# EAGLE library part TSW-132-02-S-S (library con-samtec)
THROUGH-HOLE .025" SQ POST HEADER Source: Samtec TSW.pdf
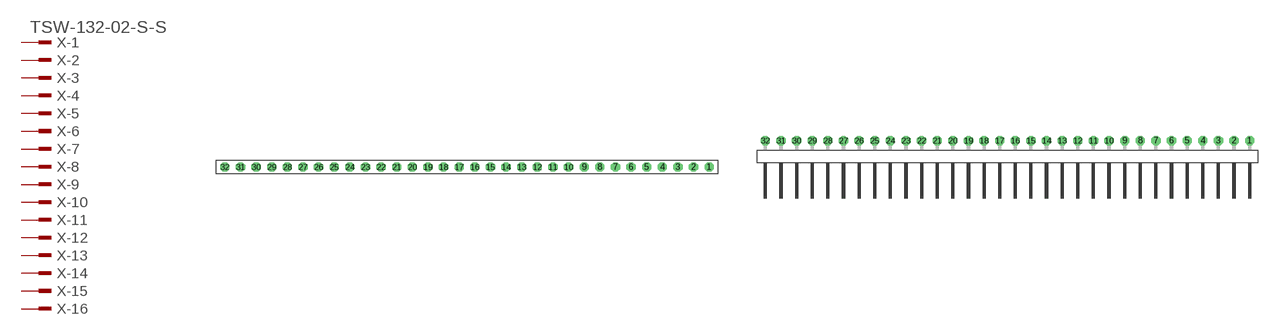
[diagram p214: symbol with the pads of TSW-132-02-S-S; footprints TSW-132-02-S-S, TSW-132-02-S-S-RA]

Designator prefix X; gates -1=MPINV -2=MPIN -3=MPIN -4=MPIN -5=MPIN -6=MPIN -7=MPIN -8=MPIN -9=MPIN -10=MPIN -11=MPIN -12=MPIN -13=MPIN -14=MPIN -15=MPIN -16=MPIN -17=MPIN -18=MPIN -19=MPIN -20=MPIN -21=MPIN -22=MPIN -23=MPIN -24=MPIN -25=MPIN -26=MPIN -27=MPIN -28=MPIN -29=MPIN -30=MPIN -31=MPIN -32=MPIN

## TSW-132-02-S-S (OC_FARNELL: unknown; OC_NEWARK: unknown)  [TSW-132-02-S-S]
1  -1:1  pas
2  -2:1  pas
3  -3:1  pas
4  -4:1  pas
5  -5:1  pas
6  -6:1  pas
7  -7:1  pas
8  -8:1  pas
9  -9:1  pas
10  -10:1  pas
11  -11:1  pas
12  -12:1  pas
13  -13:1  pas
14  -14:1  pas
15  -15:1  pas
16  -16:1  pas
17  -17:1  pas
18  -18:1  pas
19  -19:1  pas
20  -20:1  pas
21  -21:1  pas
22  -22:1  pas
23  -23:1  pas
24  -24:1  pas
25  -25:1  pas
26  -26:1  pas
27  -27:1  pas
28  -28:1  pas
29  -29:1  pas
30  -30:1  pas
31  -31:1  pas
32  -32:1  pas

## TSW-132-02-S-S-RA (OC_FARNELL: unknown; OC_NEWARK: unknown)  [TSW-132-02-S-S-RA]
Pads as for TSW-132-02-S-S

## Footprint TSW-132-02-S-S (pad centres in mm)
THROUGH-HOLE .025" SQ POST HEADER Source: Samtec TSW.pdf
drill 1 pad 1.5 octagon: 1 39.37,0; 2 36.83,0; 3 34.29,0; 4 31.75,0; 5 29.21,0; 6 26.67,0; 7 24.13,0; 8 21.59,0; 9 19.05,0; 10 16.51,0; 11 13.97,0; 12 11.43,0; 13 8.89,0; 14 6.35,0; 15 3.81,0; 16 1.27,0; 17 -1.27,0; 18 -3.81,0; 19 -6.35,0; 20 -8.89,0; 21 -11.43,0; 22 -13.97,0; 23 -16.51,0; 24 -19.05,0; 25 -21.59,0; 26 -24.13,0; 27 -26.67,0; 28 -29.21,0; 29 -31.75,0; 30 -34.29,0; 31 -36.83,0; 32 -39.37,0

## Footprint TSW-132-02-S-S-RA (pad centres in mm)
THROUGH-HOLE .025" SQ POST HEADER Source: Samtec TSW.pdf
drill 1 pad 1.5 octagon: 1 39.37,1.524; 2 36.83,1.524; 3 34.29,1.524; 4 31.75,1.524; 5 29.21,1.524; 6 26.67,1.524; 7 24.13,1.524; 8 21.59,1.524; 9 19.05,1.524; 10 16.51,1.524; 11 13.97,1.524; 12 11.43,1.524; 13 8.89,1.524; 14 6.35,1.524; 15 3.81,1.524; 16 1.27,1.524; 17 -1.27,1.524; 18 -3.81,1.524; 19 -6.35,1.524; 20 -8.89,1.524; 21 -11.43,1.524; 22 -13.97,1.524; 23 -16.51,1.524; 24 -19.05,1.524; 25 -21.59,1.524; 26 -24.13,1.524; 27 -26.67,1.524; 28 -29.21,1.524; 29 -31.75,1.524; 30 -34.29,1.524; 31 -36.83,1.524; 32 -39.37,1.524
